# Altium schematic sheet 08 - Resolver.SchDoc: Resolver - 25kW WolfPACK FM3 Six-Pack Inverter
size 431 x 279 mm; Date: 01/2024; DocumentNumber: CRD25DA12N-FMC; Revision: 1.2; SheetNumber: 8; SheetTotal: 8; SheetSize: B
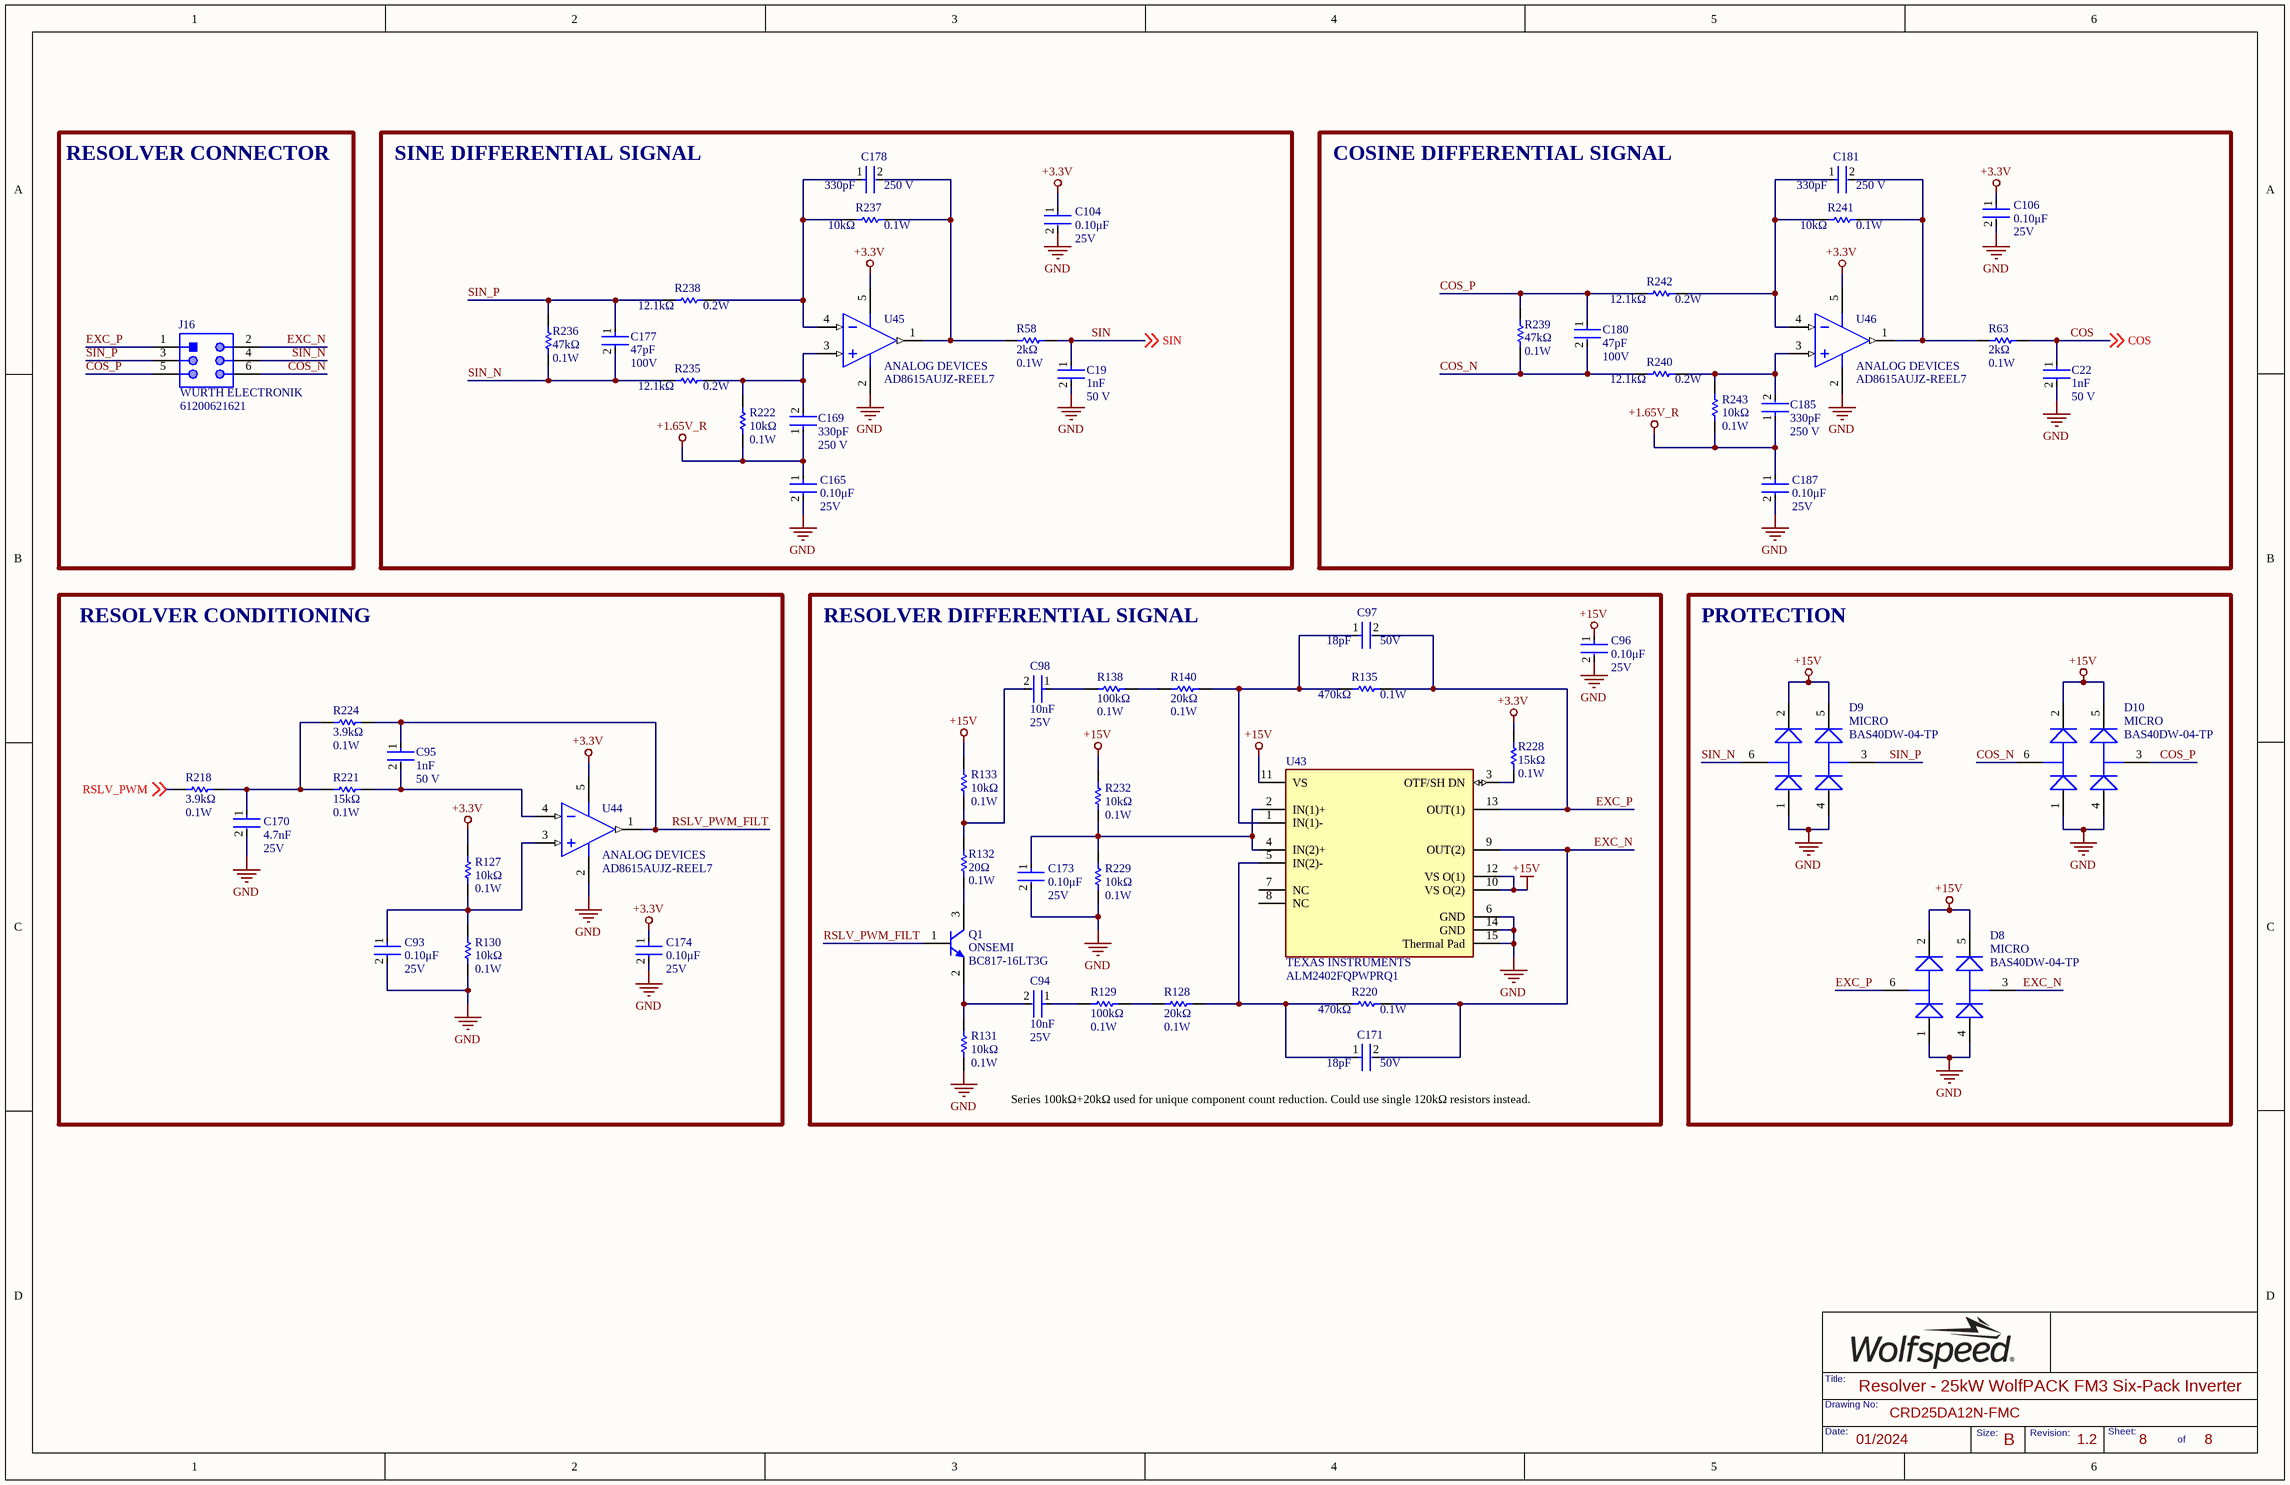
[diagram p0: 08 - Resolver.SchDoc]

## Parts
C19  Capacitance: 1nF  Voltage Rating: 50 V  [FP-C0603C-CF-IPC_B]  (hidden comment: C0603C102K5RACAUTO)
C22  Capacitance: 1nF  Voltage Rating: 50 V  [FP-C0603C-CF-IPC_B]  (hidden comment: C0603C102K5RACAUTO)
C93  Voltage Rating: 25V  Capacitance: 0.10μF  [FP-C0603C-CF-IPC_B]  (hidden comment: C0603C104K3RACTU)
C94  value 10nF  Voltage Rating: 25V  [FP-C0603C-CF-IPC_B]  (hidden comment: CL10B103KA8WPNC)
C95  Capacitance: 1nF  Voltage Rating: 50 V  [FP-C0603C-CF-IPC_B]  (hidden comment: C0603C102K5RACAUTO)
C96  Voltage Rating: 25V  Capacitance: 0.10μF  [FP-C0603C-CF-IPC_B]  (hidden comment: C0603C104K3RACTU)
C97  Capacitance: 18pF  Voltage Rating: 50V  [FP-C0603C-CF-IPC_B]  (hidden comment: 06035A180JAT2A)
C98  value 10nF  Voltage Rating: 25V  [FP-C0603C-CF-IPC_B]  (hidden comment: CL10B103KA8WPNC)
C104  Voltage Rating: 25V  Capacitance: 0.10μF  [FP-C0603C-CF-IPC_B]  (hidden comment: C0603C104K3RACTU)
C106  Voltage Rating: 25V  Capacitance: 0.10μF  [FP-C0603C-CF-IPC_B]  (hidden comment: C0603C104K3RACTU)
C165  Voltage Rating: 25V  Capacitance: 0.10μF  [FP-C0603C-CF-IPC_B]  (hidden comment: C0603C104K3RACTU)
C169  value 330pF  Voltage Rating: 250 V  [FP-C0603C-CF-IPC_B]  (hidden comment: C0603C331JAGAC7867)
C170  Voltage Rating: 25V  Capacitance: 4.7nF  [FP-C0603C-CF-IPC_B]  (hidden comment: C0603C472K3RAC7867)
C171  Capacitance: 18pF  Voltage Rating: 50V  [FP-C0603C-CF-IPC_B]  (hidden comment: 06035A180JAT2A)
C173  Voltage Rating: 25V  Capacitance: 0.10μF  [FP-C0603C-CF-IPC_B]  (hidden comment: C0603C104K3RACTU)
C174  Voltage Rating: 25V  Capacitance: 0.10μF  [FP-C0603C-CF-IPC_B]  (hidden comment: C0603C104K3RACTU)
C177  Capacitance: 47pF  Voltage Rating (DC): 100V  [FP-C0603C-CF-IPC_B]  (hidden comment: C0603C470J1GACTU)
C178  value 330pF  Voltage Rating: 250 V  [FP-C0603C-CF-IPC_B]  (hidden comment: C0603C331JAGAC7867)
C180  Capacitance: 47pF  Voltage Rating (DC): 100V  [FP-C0603C-CF-IPC_B]  (hidden comment: C0603C470J1GACTU)
C181  value 330pF  Voltage Rating: 250 V  [FP-C0603C-CF-IPC_B]  (hidden comment: C0603C331JAGAC7867)
C185  value 330pF  Voltage Rating: 250 V  [FP-C0603C-CF-IPC_B]  (hidden comment: C0603C331JAGAC7867)
C187  Voltage Rating: 25V  Capacitance: 0.10μF  [FP-C0603C-CF-IPC_B]  (hidden comment: C0603C104K3RACTU)
D8  Manufacturer Print: MICRO  [SOT65P222X120-6N]  (hidden comment: BAS40DW-04-TP)
D9  Manufacturer Print: MICRO  [SOT65P222X120-6N]  (hidden comment: BAS40DW-04-TP)
D10  Manufacturer Print: MICRO  [SOT65P222X120-6N]  (hidden comment: BAS40DW-04-TP)
J16  Manufacturer: WURTH ELECTRONIK  [61200621621]  (hidden comment: 61200621621)
Q1  Manufacturer: ONSEMI  [ONSC-SOT-23-3-318-08_V]  (hidden comment: BC817-16LT3G)
R58  Resistance: 2kΩ  Power Rating: 0.1W  [FP-MCR03-IPC_B]  (hidden comment: RT0603DRE072KL)
R63  Resistance: 2kΩ  Power Rating: 0.1W  [FP-MCR03-IPC_B]  (hidden comment: RT0603DRE072KL)
R127  Resistance: 10kΩ  Max Power Dissipation: 0.1W  [FP-MCR03-IPC_B]  (hidden comment: ERJ3EKF1002V)
R128  Resistance: 20kΩ  Power Rating: 0.1W  [FP-MCR03-IPC_B]  (hidden comment: CRCW060320K0FKTA)
R129  Resistance: 100kΩ  Power Rating: 0.1W  [FP-MCR03-IPC_B]  (hidden comment: RC0603FR-07100KL)
R130  Resistance: 10kΩ  Max Power Dissipation: 0.1W  [FP-MCR03-IPC_B]  (hidden comment: ERJ3EKF1002V)
R131  Resistance: 10kΩ  Max Power Dissipation: 0.1W  [FP-MCR03-IPC_B]  (hidden comment: ERJ3EKF1002V)
R132  Resistance: 20Ω  Power Rating: 0.1W  [FP-MCR03-IPC_B]  (hidden comment: RC0603JR-0720RL)
R133  Resistance: 10kΩ  Max Power Dissipation: 0.1W  [FP-MCR03-IPC_B]  (hidden comment: ERJ3EKF1002V)
R135  Resistance: 470kΩ  Power Rating: 0.1W  [FP-MCR03-IPC_B]  (hidden comment: RC0603FR-07470KL)
R138  Resistance: 100kΩ  Power Rating: 0.1W  [FP-MCR03-IPC_B]  (hidden comment: RC0603FR-07100KL)
R140  Resistance: 20kΩ  Power Rating: 0.1W  [FP-MCR03-IPC_B]  (hidden comment: CRCW060320K0FKTA)
R218  Resistance: 3.9kΩ  Power Rating: 0.1W  [FP-MCR03-IPC_B]  (hidden comment: ERJ3EKF3901V)
R220  Resistance: 470kΩ  Power Rating: 0.1W  [FP-MCR03-IPC_B]  (hidden comment: RC0603FR-07470KL)
R221  Resistance: 15kΩ  Power Rating: 0.1W  [FP-MCR03-IPC_B]  (hidden comment: ERA-3AED153V)
R222  Resistance: 10kΩ  Max Power Dissipation: 0.1W  [FP-MCR03-IPC_B]  (hidden comment: ERJ3EKF1002V)
R224  Resistance: 3.9kΩ  Power Rating: 0.1W  [FP-MCR03-IPC_B]  (hidden comment: ERJ3EKF3901V)
R228  Resistance: 15kΩ  Power Rating: 0.1W  [FP-MCR03-IPC_B]  (hidden comment: ERA-3AED153V)
R229  Resistance: 10kΩ  Max Power Dissipation: 0.1W  [FP-MCR03-IPC_B]  (hidden comment: ERJ3EKF1002V)
R232  Resistance: 10kΩ  Max Power Dissipation: 0.1W  [FP-MCR03-IPC_B]  (hidden comment: ERJ3EKF1002V)
R235  Resistance: 12.1kΩ  Max Power Dissipation: 0.2W  [FP-MCR03-IPC_B]  (hidden comment: ERJ-PB3B1212V)
R236  Resistance: 47kΩ  Power Rating: 0.1W  [FP-MCR03-IPC_B]  (hidden comment: RC0603FR-0747KL)
R237  Resistance: 10kΩ  Max Power Dissipation: 0.1W  [FP-MCR03-IPC_B]  (hidden comment: ERJ3EKF1002V)
R238  Resistance: 12.1kΩ  Max Power Dissipation: 0.2W  [FP-MCR03-IPC_B]  (hidden comment: ERJ-PB3B1212V)
R239  Resistance: 47kΩ  Power Rating: 0.1W  [FP-MCR03-IPC_B]  (hidden comment: RC0603FR-0747KL)
R240  Resistance: 12.1kΩ  Max Power Dissipation: 0.2W  [FP-MCR03-IPC_B]  (hidden comment: ERJ-PB3B1212V)
R241  Resistance: 10kΩ  Max Power Dissipation: 0.1W  [FP-MCR03-IPC_B]  (hidden comment: ERJ3EKF1002V)
R242  Resistance: 12.1kΩ  Max Power Dissipation: 0.2W  [FP-MCR03-IPC_B]  (hidden comment: ERJ-PB3B1212V)
R243  Resistance: 10kΩ  Max Power Dissipation: 0.1W  [FP-MCR03-IPC_B]  (hidden comment: ERJ3EKF1002V)
U43  Manufacturer: TEXAS INSTRUMENTS  [FP-PWP0014H-MFG]  (hidden comment: ALM2402FQPWPRQ1)
U44  Manufacturer: ANALOG DEVICES  [ADI-UJ-5_M]  (hidden comment: AD8615AUJZ-REEL7)
U45  Manufacturer: ANALOG DEVICES  [ADI-UJ-5_M]  (hidden comment: AD8615AUJZ-REEL7)
U46  Manufacturer: ANALOG DEVICES  [ADI-UJ-5_M]  (hidden comment: AD8615AUJZ-REEL7)

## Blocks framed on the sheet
RESOLVER CONNECTOR: J16
SINE DIFFERENTIAL SIGNAL: C19 C104 C165 C169 C177 C178 R58 R222 R235-R238 U45
COSINE DIFFERENTIAL SIGNAL: C22 C106 C180 C181 C185 C187 R63 R239-R243 U46
RESOLVER CONDITIONING: C93 C95 C170 C174 R127 R130 R218 R221 R224 U44
RESOLVER DIFFERENTIAL SIGNAL: C94 C96-C98 C171 C173 Q1 R128 R129 R131-R133 R135 R138 R140 R220 R228 R229 R232 U43
PROTECTION: D8-D10

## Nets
+1.65V_R: C165.1 C169.1 C185.1 C187.1 R222.1 R243.1
+3.3V: C104.1 C106.1 C174.1 R127.2 R228.2 U44.5(+V) U45.5(+V) U46.5(+V)
+15V: C96.1 D8.2(C1) D8.5(C2) D9.2(C1) D9.5(C2) D10.2(C1) D10.5(C2) R133.2 R232.2 U43.10(VS_O(2)) U43.11(VS) U43.12(VS_O(1))
GND: C19.2 C22.2 C93.2 C96.2 C104.2 C106.2 C165.2 C170.2 C173.2 C174.2 C187.2 D8.1(A1) D8.4(A2) D9.1(A1) D9.4(A2) D10.1(A1) D10.4(A2) R130.1 R131.1 R229.1 U43.6(GND) U43.14(GND) U43.15(Thermal_Pad) U44.2(-V) U45.2(-V) U46.2(-V)
COS: C22.1 R63.2 ; off-sheet COS
COS_N: C180.2 D10.6(AC1) J16.6 R239.1 R240.1
COS_P: C180.1 D10.3(AC2) J16.5 R239.2 R242.1
EXC_N: C171.2 D8.3(AC2) J16.2 R220.2 U43.9(OUT(2))
EXC_P: C97.2 D8.6(AC1) J16.1 R135.2 U43.13(OUT(1))
RSLV_PWM: R218.1 ; off-sheet RSLV_PWM
RSLV_PWM_FILT: C95.1 Q1.1(B) R224.2 U44.1(OUT)
SIN: C19.1 R58.2 ; off-sheet SIN
SIN_N: C177.2 D9.6(AC1) J16.4 R235.1 R236.1
SIN_P: C177.1 D9.3(AC2) J16.3 R236.2 R238.1
NetC93_1: C93.1 R127.1 R130.2 U44.3(+IN)
NetC94_1: C94.1 R129.2
NetC94_2: C94.2 Q1.2(E) R131.2
NetC95_2: C95.2 R221.1 U44.4(-IN)
NetC97_1: C97.1 R135.1 R140.1 U43.1(IN(1)-)
NetC98_1: C98.1 R138.2
NetC98_2: C98.2 R132.2 R133.1
NetC169_2: C169.2 R222.2 R235.2 U45.3(+IN)
NetC170_1: C170.1 R218.2 R221.2 R224.1
NetC171_1: C171.1 R128.1 R220.1 U43.5(IN(2)-)
NetC173_1: C173.1 R229.2 R232.1 U43.2(IN(1)+) U43.4(IN(2)+)
NetC178_1: C178.1 R237.2 R238.2 U45.4(-IN)
NetC178_2: C178.2 R58.1 R237.1 U45.1(OUT)
NetC181_1: C181.1 R241.2 R242.2 U46.4(-IN)
NetC181_2: C181.2 R63.1 R241.1 U46.1(OUT)
NetC185_2: C185.2 R240.2 R243.2 U46.3(+IN)
NetQ1_3: Q1.3(C) R132.1
NetR128_2: R128.2 R129.1
NetR138_1: R138.1 R140.2
NetR228_1: R228.1 U43.3(OTF/SH_DN)

Not connected (* = marked no-connect by the designer): U43 7(NC) 8(NC)

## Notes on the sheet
- (near C171) Series 100kΩ+20kΩ used for unique component count reduction. Could use single 120kΩ resistors instead.

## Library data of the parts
C19 C22 C95 = CMP-2006-03716-2: CAP CER 1000PF 50V X7R 0603; Manufacturer: KEMET; Material: Ceramic; Automotive Grade: Grade 1; Value: 1nF; Tolerance: 0.1; Temperature Coefficient: 30ppm/°C
C93 C96 C104 C106 C165 C173 C174 C187 = CMP-2006-03057-2: CAP CER 0.1UF 25V X7R 0603; Manufacturer: KEMET; Value: 0.10μF; Material: Ceramic; Tolerance: 0.1; Temperature Coefficient: 30ppm/°C; Automotive Grade: Grade 1
C94 C98 = CL10B103KA8WPNC: CAP CER 10000PF 25V X7R 0603; Manufacturer: SAMSUNG; Tolerance: 10%
C97 C171 = 06035A180JAT2A: CAP CER 18PF 50V C0G/NP0 0603; Manufacturer: KYOCERA AVX; Dielectric Material: Ceramic; Tolerance: 5%; Dielectric: C0G; Insulation Resistance: 100GR; Temperature Coefficient: 30ppm/°C
C169 C178 C181 C185 = CMP-03020-020944-2: CAP CER 330PF 250V C0G/NP0 0603; Manufacturer: KEMET; Material: Ceramic; Temperature Coefficient: 30ppm/°C; Tolerance: 0.05; Automotive Grade: Grade 1; Temperature Characteristic: C0G
C170 = C0603C472K3RAC7867: CAP CER 4700PF 25V 10% X7R 0603; Manufacturer: KEMET; Manufacturer Part Number: C0603C472K3RACTU; Dielectric Material: Ceramic; Value: 4.7nF
C177 C180 = C0603C470J1GACTU: CAP CER 47PF 100V C0G/NP0 0603; Manufacturer: KEMET; Dielectric Material: Ceramic; Tolerance: 5%; Dielectric: C0G; Temperature Coefficient: 30ppm/°C; Dissipation Factor: 0.1%
D8-D10 = BAS40DW-04-TP: DIODE ARRAY SCHOTTKY 40V SOT363; Manufacturer_Name: Micro Commercial Components (MCC); Manufacturer: MICRO COMMERCIAL; Class: DIO
J16 = CMP-1502-00000-1: CONN HEADER VERT 6POS 2.54MM; Withstanding Voltage: 500VAC; Working Voltage: 250VAC; Pin Number: 6; Gender: Male; Contact Resistance: 20mOhm
Q1 = CMP-1048-00731-1: TRANS NPN 45V 0.5A SOT23-3; IC Continuous (A): 0.5; Packing: Tape and Reel; fT Min (MHz): 100
R58 R63 = RT0603DRE072KL: RES SMD 2K OHM 0.5% 1/10W 0603; Manufacturer: YAGEO; Temperature Coefficient: 50ppm/°C; Voltage Rating: 75V; Max Power Dissipation: 100mW; Voltage Rating (DC): 50V; Value: 2kΩ
R127 R130 R131 R133 R222 R229 R232 R237 R241 R243 = ERJ3EKF1002V: RES SMD 10K OHM 1% 1/10W 0603; Manufacturer: PANASONIC; Manufacturer Part Number: ERJ-3EKF1002V; Temperature Coefficient: 100ppm/°C; Power Rating: 100mW; Voltage Rating: 75V; Value: 10kΩ
R128 R140 = CRCW060320K0FKTA: RES SMD 20K OHM 1% 1/10W 0603; Manufacturer: VISHAY DALE; Temperature Coefficient: 100ppm/°C; Voltage Rating: 75V; Max Power Dissipation: 100mW; Value: 20kΩ
R129 R138 = RC0603FR-07100KL: RES 100K OHM 1% 1/10W 0603; Manufacturer: YAGEO; Temperature Coefficient: 100ppm/°C; Voltage Rating: 50V; Working Voltage: 75V; Max Power Dissipation: 100mW; Value: 100kΩ
R132 = RC0603JR-0720RL: RES 20 OHM 5% 1/10W 0603; Manufacturer: YAGEO; Temperature Coefficient: 100ppm/°C; Voltage Rating (DC): 50V; Voltage Rating: 75V; Max Power Dissipation: 100mW; Value: 20Ω
R135 R220 = RC0603FR-07470KL: RES 470K OHM 1% 1/10W 0603; Manufacturer: YAGEO; Temperature Coefficient: 100ppm/°C; Voltage Rating: 50V; Max Power Dissipation: 100mW; Value: 470kΩ
R218 R224 = ERJ3EKF3901V: RES SMD 3.9K OHM 1% 1/10W 0603; Manufacturer: PANASONIC; Manufacturer Part Number: ERJ-3EKF3901V; Temperature Coefficient: 100ppm/°C; Voltage Rating: 75V; Max Power Dissipation: 100mW; Value: 3.9kΩ
R221 R228 = ERA-3AED153V: RES SMD 15K OHM 0.5% 1/10W 0603; Manufacturer: PANASONIC; Voltage Rating: 75V; Temperature Coefficient: 25ppm/°C; Max Power Dissipation: 100mW; Value: 15kΩ
R235 R238 R240 R242 = ERJ-PB3B1212V: RES SMD 12.1K OHM 0.1% 1/5W 0603; Manufacturer: PANASONIC; Temperature Coefficient: 50ppm/°C; Value: 12.1kΩ
R236 R239 = RC0603FR-0747KL: RES 47K OHM 1% 1/10W 0603; Manufacturer: YAGEO; Temperature Coefficient: 100ppm/°C; Voltage Rating: 50V; Max Power Dissipation: 100mW; Value: 47kΩ
U43 = CMP-04895-000282-1: IC POWER 2 CIRCUIT 14HTSSOP
U44-U46 = CMP-0384-02059-2: IC OPAMP GP 1 CIRCUIT TSOT23-5; Generic Part Number: AD8615; Iq/Amp: 1.7mA; V Span Max: 6V; Amplifiers Per Package: 1; Small Signal Bandwidth: 23MHz; Input Offset Voltage: 80uV; V Span Min: 2.7V; Slew Rate: 12V/us; Input Bias Current: 200fA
